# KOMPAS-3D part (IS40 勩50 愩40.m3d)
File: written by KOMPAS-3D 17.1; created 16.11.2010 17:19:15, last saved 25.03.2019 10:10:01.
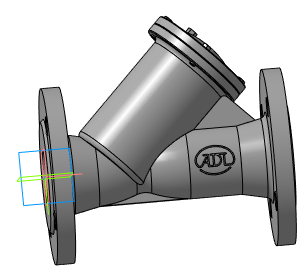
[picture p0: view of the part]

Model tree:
1. Плоскость XY
2. Плоскость ZX
3. Плоскость ZY
4. Ось X
5. Ось Y
6. Ось Z
7. Начало координат
8. Операция без истории:2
